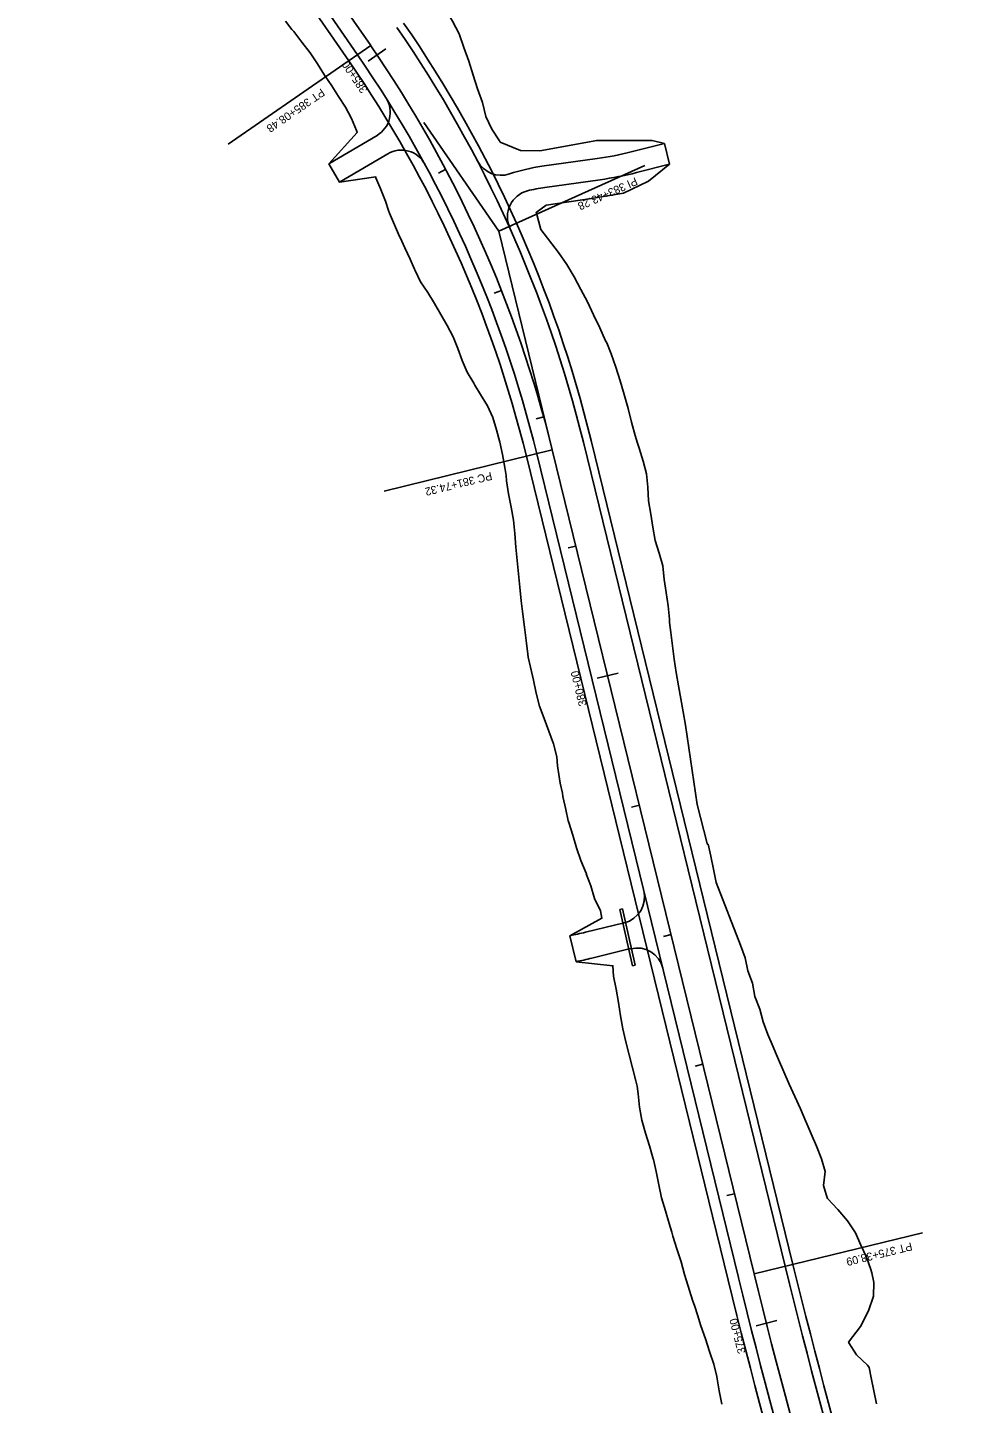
# Model space of a CAD drawing. Extents: x 948761 to 996004, y 1858548 to 1925175.
# Drawn here: x 960302 to 960998, y 1908384 to 1909416 of the extents above; entities that cross this region are included whole.
import ezdxf

# ---------------------------------------------------------------- set-up
doc = ezdxf.new("R2010")
doc.units = 0
for name, color, linetype in [('R_Drainage', 7, 'Continuous'), ('R_Horz Alg', 7, 'Continuous'), ('R_Horz Alg Annot', 7, 'Continuous'), ('R_Proposed Const Limits', 7, 'Continuous'), ('R_Proposed Road', 7, 'Continuous')]:
    doc.layers.add(name, color=color, linetype=linetype)

msp = doc.modelspace()

# ---------------------------------------------------------------- linework, layer by layer
at = {"layer": 'R_Drainage'}
for p, q in [((960748, 1908754.7), (960746.1, 1908754.3)), ((960746.1, 1908754.3), (960755.5, 1908712.1)), ((960757.5, 1908712.6), (960748, 1908754.7)), ((960755.5, 1908712.1), (960757.5, 1908712.6))]:
    msp.add_line(p, q, dxfattribs=at)
at = {"layer": 'R_Horz Alg'}
for p, q in [((960559.2, 1909402.1), (960318.1, 1909750.9)), ((960846.8, 1908481), (960695.4, 1909099))]:
    msp.add_line(p, q, dxfattribs=at)
for centre, radius, start, end in [((959805, 1908880.8), 916.7, 13.7645, 34.6498), ((965298.8, 1909571.6), 4583.7, 193.7645, 199.1777)]:
    msp.add_arc(centre, radius, start, end, dxfattribs=at)
at = {"layer": 'R_Horz Alg Annot'}
for q in [(960598.9, 1909344.6), (960695.4, 1909099)]:
    msp.add_line((960655.2, 1909263.1), q, dxfattribs=at)
for points in [[(960559.2, 1909402.1), (960452.2, 1909328.2)], [(960557.3, 1909390.6), (960570.6, 1909399.6)], [(960610.1, 1909306.6), (960615.4, 1909309.4)], [(960655.2, 1909263.1), (960764.7, 1909312.3)], [(960651.7, 1909216.4), (960657.3, 1909218.6)], [(960683.2, 1909122.2), (960689, 1909123.8)], [(960695.4, 1909099), (960569.2, 1909068)], [(960707.3, 1909025.4), (960713.1, 1909026.8)], [(960729.1, 1908927.8), (960744.7, 1908931.6)], [(960754.9, 1908831.1), (960760.7, 1908832.5)], [(960778.7, 1908734), (960784.5, 1908735.4)], [(960802.5, 1908636.8), (960808.3, 1908638.3)], [(960826.3, 1908539.7), (960832.1, 1908541.1)], [(960846.8, 1908481), (960973.1, 1908511.9)], [(960848.3, 1908442.1), (960863.8, 1908446)]]:
    msp.add_lwpolyline(points, dxfattribs=at)
at = {"layer": 'R_Proposed Const Limits'}
for points in [[(960650, 1909339.5), (960645.4, 1909348.9), (960642.9, 1909359.6), (960639.3, 1909369.7), (960635.9, 1909380), (960632.7, 1909390.4), (960629.1, 1909400.7), (960625.5, 1909411), (960620.4, 1909420.4), (960615.1, 1909429.7), (960609.7, 1909438.9), (960602.9, 1909446.3), (960595.2, 1909453.1), (960587.4, 1909459.9), (960579.6, 1909466.7), (960577.9, 1909468.1), (960571.8, 1909473.4), (960563.9, 1909480.1), (960548.2, 1909493.6)], [(960527.8, 1909313.6), (960549, 1909337), (960548.5, 1909338.6), (960544.8, 1909347.5), (960540.2, 1909355.9), (960535, 1909363.9), (960529.9, 1909372), (960524.5, 1909380), (960519.1, 1909388.4), (960513.6, 1909396.8), (960507.5, 1909404.7), (960501.4, 1909412.6), (960500, 1909414.3), (960495.2, 1909420.5)], [(960656.2, 1909329.7), (960655.7, 1909330.7), (960650, 1909339.5)], [(960779.5, 1909328.7), (960770.2, 1909331.1), (960748.7, 1909331.1), (960728.7, 1909331), (960686, 1909323.2), (960671.5, 1909323.4), (960656.2, 1909329.7)], [(960690.7, 1909282.5), (960724.7, 1909287.5), (960748.7, 1909291.5), (960767.6, 1909300.5), (960783.4, 1909313.2)], [(960708.5, 1908734.6), (960732.6, 1908747.7), (960731.5, 1908753.3), (960727, 1908762.5), (960724.2, 1908772.1), (960720.9, 1908780.9), (960720.9, 1908780.9), (960721.2, 1908781), (960721.1, 1908781), (960720.9, 1908781.6), (960716.7, 1908790.9), (960713.5, 1908800.4), (960710.8, 1908810), (960707.7, 1908819.6), (960707.3, 1908820.8), (960705.5, 1908829.3), (960703.4, 1908839.1), (960703, 1908841.4), (960701.4, 1908848.9), (960699.7, 1908858.8), (960699.4, 1908862.1), (960698.8, 1908868.8), (960696.3, 1908878.5), (960692.7, 1908887.9), (960689.4, 1908897.4), (960685.7, 1908906.8), (960683.4, 1908916.5), (960681.2, 1908926.3), (960679, 1908936.1), (960677.3, 1908943.5), (960676.9, 1908945.8), (960675.7, 1908955.9), (960674.5, 1908965.9), (960673.2, 1908975.8), (960671.9, 1908985.8), (960670.9, 1908995.9), (960669.9, 1909005.9), (960668.9, 1909016), (960668, 1909026), (960667.3, 1909036.2), (960666.2, 1909046.2), (960664.6, 1909056.1), (960662.6, 1909065.9), (960661, 1909075.8), (960660.8, 1909079.8), (960659.8, 1909085.8), (960658, 1909095.4), (960656.1, 1909104.8), (960653.5, 1909114.1), (960650.8, 1909123.3), (960646.7, 1909132.1), (960641.4, 1909140.5), (960637.3, 1909147.6), (960636.6, 1909148.9), (960631.5, 1909157.3), (960627.7, 1909166), (960624.5, 1909175), (960621.1, 1909183.8), (960616.5, 1909192.2), (960611.7, 1909200.5), (960607, 1909208.8), (960602.1, 1909217), (960596.5, 1909224.9), (960592.5, 1909233.4), (960591.9, 1909234.6), (960588.8, 1909242.1), (960584.7, 1909250.5), (960581.2, 1909258.3), (960580.8, 1909259.1), (960577.1, 1909267.8), (960573.3, 1909276.5), (960572.4, 1909278.6), (960570.3, 1909285.5), (960566.7, 1909294.3), (960563.1, 1909303.1), (960562.9, 1909303.8), (960561.3, 1909303.6), (960535.8, 1909299.8)], [(960686.9, 1909264.2), (960684.1, 1909274.4), (960683.7, 1909275.9), (960683.2, 1909277.1), (960690.7, 1909282.5)], [(960804.1, 1908832.9), (960795.4, 1908892.5), (960793.6, 1908902.4), (960791.8, 1908912.2), (960790, 1908922.1), (960788.2, 1908931.9), (960786.9, 1908941.9), (960785.5, 1908951.9), (960784.4, 1908961.9), (960783.4, 1908969.5), (960783.2, 1908971.9), (960782.2, 1908981.9), (960780.8, 1908991.9), (960779.3, 1909001.8), (960778.4, 1909011.9), (960775.6, 1909021.5), (960772.6, 1909031.1), (960770.8, 1909040.9), (960769.2, 1909050.8), (960767.5, 1909060.7), (960767.1, 1909070.9), (960766, 1909080.9), (960763.6, 1909090.6), (960760.6, 1909100.2), (960759.4, 1909104), (960757.6, 1909109.7), (960754.9, 1909119.8), (960752.2, 1909130.1), (960749.3, 1909140.4), (960746.4, 1909150.7), (960743.1, 1909160.9), (960739.6, 1909170.9), (960736.2, 1909179.3), (960735.4, 1909180.8), (960731.1, 1909190.6), (960726.3, 1909200.2), (960721.8, 1909209.9), (960716.7, 1909219.3), (960711.8, 1909228.8), (960706.4, 1909238.1), (960700, 1909246.9), (960686.9, 1909264.2)], [(960818.2, 1908774.6), (960816.4, 1908784.4), (960814.3, 1908794.2), (960812.2, 1908803.2), (960812, 1908803.2), (960811.7, 1908803.1), (960811.7, 1908803.2), (960811.6, 1908803.8), (960809.1, 1908813.5), (960806.5, 1908823.2), (960804.1, 1908832.9)], [(960938.5, 1908383.6), (960936.7, 1908393.3), (960934.7, 1908403), (960933.1, 1908410.8), (960933.1, 1908410.8), (960931.9, 1908412.5), (960923.5, 1908420.4), (960917.9, 1908429.2), (960917.7, 1908429.7), (960926.6, 1908441.6), (960932.7, 1908453.4), (960936.3, 1908464.4), (960936.6, 1908474.6), (960935.1, 1908481.8), (960934.4, 1908484.2), (960931.2, 1908493.5), (960926.9, 1908502.6), (960922.9, 1908511.9), (960916.8, 1908520.7), (960909.5, 1908529.2), (960901.8, 1908537.6), (960900.9, 1908540.6), (960898.8, 1908547.2), (960900.2, 1908557.8), (960897.4, 1908567.4), (960893.6, 1908576.8), (960889.5, 1908586.1), (960885.8, 1908594.8), (960885.6, 1908595.4), (960881.5, 1908604.7), (960877.4, 1908614), (960873.1, 1908623.3), (960869.1, 1908632.6), (960865.1, 1908641.9), (960862.9, 1908647.1), (960861.2, 1908651.2), (960857.2, 1908660.5), (960853.7, 1908670), (960851, 1908679.6), (960847.4, 1908689), (960845.7, 1908698.9), (960842.2, 1908708.3), (960840.1, 1908718.1), (960836.5, 1908727.6), (960818.2, 1908774.6)], [(960822.5, 1908383.4), (960820.5, 1908393.3), (960818.8, 1908403.7), (960818.8, 1908404), (960816.5, 1908413.2), (960813.4, 1908422.8), (960810.3, 1908432.4), (960806.9, 1908442), (960804.2, 1908450.4), (960802.2, 1908456.5), (960800.6, 1908461.3), (960796.1, 1908475.7), (960794.6, 1908480.5), (960792, 1908490.1), (960788.9, 1908499.7), (960785.8, 1908509.2), (960785.1, 1908512.2), (960783.1, 1908518.9), (960780.2, 1908528.4), (960777.4, 1908538), (960775.3, 1908547.8), (960773.4, 1908557.7), (960771.2, 1908566.7), (960771, 1908567.4), (960768.3, 1908577), (960765.2, 1908586.5), (960762.6, 1908596.2), (960760.9, 1908606.1), (960759.8, 1908616.1), (960759, 1908621.7), (960758, 1908625.9), (960755.5, 1908635.6), (960753, 1908645.3), (960750.6, 1908655), (960748.3, 1908664.8), (960746.6, 1908674.6), (960745, 1908684.6), (960743.4, 1908694.5), (960741.2, 1908704.2), (960740.9, 1908712.1), (960713.2, 1908715.1)]]:
    msp.add_lwpolyline(points, dxfattribs=at)
at = {"layer": 'R_Proposed Road'}
for p, q in [((960542.7, 1909390.7), (960301.6, 1909739.5)), ((960549.3, 1909395.2), (960308.2, 1909744)), ((960527.8, 1909313.6), (960563.9, 1909334.8)), ((960779.5, 1909328.7), (960754.6, 1909322.4)), ((960783.4, 1909313.2), (960779.5, 1909328.7)), ((960535.8, 1909299.8), (960572, 1909321)), ((960687.6, 1909311.7), (960729, 1909317.4)), ((960535.8, 1909299.8), (960527.8, 1909313.6)), ((960783.4, 1909313.2), (960758.5, 1909306.9)), ((960689.8, 1909295.8), (960731.2, 1909301.5)), ((960870.1, 1908486.7), (960718.7, 1909104.7)), ((960875.9, 1908488.1), (960724.6, 1909106.1)), ((960827.4, 1908476.3), (960676, 1909094.2)), ((960835.2, 1908478.2), (960683.8, 1909096.1)), ((960720.2, 1908737.2), (960749.4, 1908744.3)), ((960708.5, 1908734.6), (960713.2, 1908715.1)), ((960725, 1908717.7), (960754.1, 1908724.9))]:
    msp.add_line(p, q, dxfattribs=at)
for centre, radius, start, end in [((959805, 1908880.8), 940.7, 13.7645, 34.6498), ((959805, 1908880.8), 946.7, 13.7645, 34.6498), ((959805, 1908880.8), 896.7, 13.7645, 34.6498), ((959805, 1908880.8), 904.7, 13.7645, 34.6498), ((960553.8, 1909352.1), 20, 300.3696, 32.1832), ((960582.1, 1909303.8), 20, 28.556, 120.3696), ((960696.9, 1909549.2), 234, 277.894, 284.2801), ((960657, 1909324.9), 20, 207.5284, 288.64), ((960705.9, 1909179.9), 133, 97.894, 108.64), ((960696.9, 1909549.2), 250, 277.894, 284.2801), ((960705.9, 1909179.9), 117, 97.894, 104.4397), ((960681.7, 1909273.8), 20, 104.4397, 204.146), ((960744.6, 1908763.7), 20, 283.7645, 13.7645), ((960660.7, 1908980), 250, 281.0147, 283.7645), ((960758.9, 1908705.4), 20, 13.7645, 103.7645), ((960660.7, 1908980), 270, 281.1982, 283.7645), ((965298.8, 1909571.6), 4559.7, 193.7645, 199.1777), ((965298.8, 1909571.6), 4553.7, 193.7645, 199.1777), ((965298.8, 1909571.6), 4603.7, 193.7645, 199.1777), ((965298.8, 1909571.6), 4595.7, 193.7645, 199.1777)]:
    msp.add_arc(centre, radius, start, end, dxfattribs=at)

# ---------------------------------------------------------------- texts
at = {"layer": 'R_Horz Alg'}
for rotation, p in [(124.6498, (960559.6, 1909402.3)), (103.7645, (960695.9, 1909099.1)), (103.7645, (960847.3, 1908481.1))]:
    msp.add_text('+', height=1, rotation=rotation, dxfattribs=at).set_placement(p)
at = {"layer": 'R_Horz Alg Annot'}
for s, rotation, p in [('385+00', 124.1196, (960557.1, 1909369.1)), ('PT 385+08.48', 214.6498, (960522, 1909370.3)), ('PI 383+43.28', 204.2071, (960757.6, 1909303.6)), ('PC 381+74.32', 193.7645, (960649.4, 1909082.5)), ('380+00', 103.7645, (960721.3, 1908907.6)), ('PT 375+38.09', 193.7645, (960964.6, 1908504.7)), ('375+00', 104.2406, (960840.6, 1908422))]:
    msp.add_text(s, height=6, rotation=rotation, dxfattribs=at).set_placement(p)

doc.saveas('drawing.dxf')
